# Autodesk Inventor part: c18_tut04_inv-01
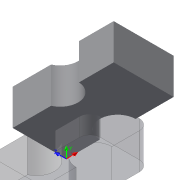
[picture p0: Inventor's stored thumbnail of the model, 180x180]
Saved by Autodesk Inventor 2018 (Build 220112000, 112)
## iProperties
Created: 2017-06
Part Number: c18_tut04_inv-01
Material: Generic
Document SubType Name: Modeling
Designer: CADCIM 00
Density: 1 g/cm^3
Appearance: Default
Author: CADCIM 00
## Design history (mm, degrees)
derived "c18_tut04_inv.ipt"
feature "Solid1::c18_tut04_inv.ipt"
tag "TaggingFeature1"
body "Solid1"
other parameters: "d2" = 10, "d4" = 0, "d5" = 6, "RAD" = 10, "FILLET" = 6
